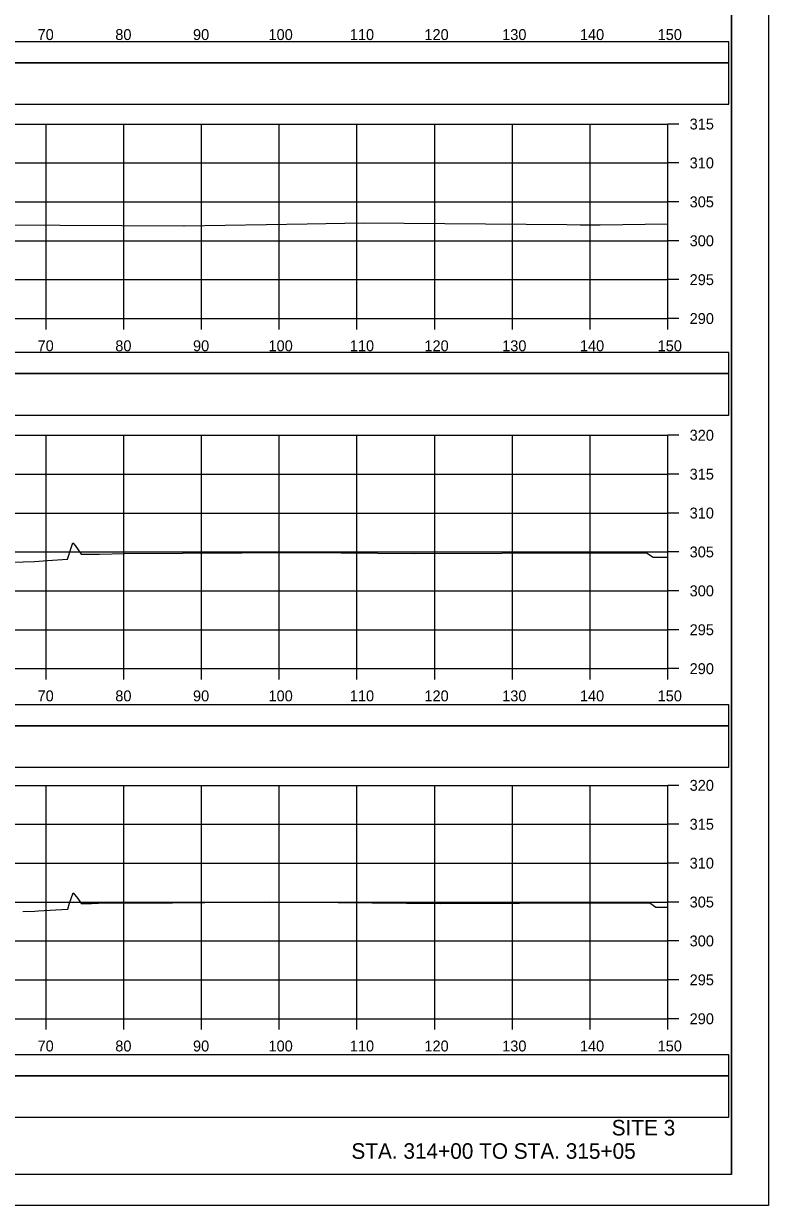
# Model space of a CAD drawing. Extents: x 1370538 to 1372872, y 376220 to 381127.
# Drawn here: x 1371442.4 to 1371538.2, y 378262.5 to 378414.4 of the extents above; entities that cross this region are included whole.
import ezdxf

# ---------------------------------------------------------------- set-up
doc = ezdxf.new("R2010")
doc.units = 0
for name, color, linetype in [('R_Border Notes', 7, 'Continuous'), ('R_Border PE', 7, 'Continuous'), ('R_Border Prem', 7, 'Continuous'), ('R_Dimension', 7, 'Continuous'), ('R_Grid', 7, 'Continuous'), ('R_Horz Alg Annot', 7, 'Continuous'), ('R_No Plot', 7, 'Continuous'), ('R_Proposed Road', 7, 'Continuous')]:
    doc.layers.add(name, color=color, linetype=linetype)

msp = doc.modelspace()

# ---------------------------------------------------------------- linework, layer by layer
at = {"layer": 'R_Border Notes'}
for q in [(1371533.47, 378471.99), (1371217.29, 378266.53)]:
    msp.add_line((1371533.47, 378266.53), q, dxfattribs=at)
at = {"layer": 'R_Border Prem'}
for p, q in [((1371525.29, 378376.53), (1371525.29, 378401.53)), ((1371526.69, 378401.53), (1371525.29, 378401.53)), ((1371526.69, 378396.53), (1371525.29, 378396.53)), ((1371526.69, 378391.53), (1371525.29, 378391.53)), ((1371526.69, 378386.53), (1371525.29, 378386.53)), ((1371526.69, 378381.53), (1371525.29, 378381.53)), ((1371225.29, 378376.53), (1371525.29, 378376.53)), ((1371445.29, 378375.13), (1371445.29, 378376.53)), ((1371455.29, 378375.13), (1371455.29, 378376.53)), ((1371465.29, 378375.13), (1371465.29, 378376.53)), ((1371475.29, 378375.13), (1371475.29, 378376.53)), ((1371485.29, 378375.13), (1371485.29, 378376.53)), ((1371495.29, 378375.13), (1371495.29, 378376.53)), ((1371505.29, 378375.13), (1371505.29, 378376.53)), ((1371515.29, 378375.13), (1371515.29, 378376.53)), ((1371525.29, 378375.13), (1371525.29, 378376.53)), ((1371526.69, 378376.53), (1371525.29, 378376.53)), ((1371525.29, 378331.53), (1371525.29, 378361.53)), ((1371526.69, 378361.53), (1371525.29, 378361.53)), ((1371526.69, 378356.53), (1371525.29, 378356.53)), ((1371526.69, 378351.53), (1371525.29, 378351.53)), ((1371526.69, 378346.53), (1371525.29, 378346.53)), ((1371526.69, 378341.53), (1371525.29, 378341.53)), ((1371526.69, 378336.53), (1371525.29, 378336.53)), ((1371225.29, 378331.53), (1371525.29, 378331.53)), ((1371445.29, 378330.13), (1371445.29, 378331.53)), ((1371455.29, 378330.13), (1371455.29, 378331.53)), ((1371465.29, 378330.13), (1371465.29, 378331.53)), ((1371475.29, 378330.13), (1371475.29, 378331.53)), ((1371485.29, 378330.13), (1371485.29, 378331.53)), ((1371495.29, 378330.13), (1371495.29, 378331.53)), ((1371505.29, 378330.13), (1371505.29, 378331.53)), ((1371515.29, 378330.13), (1371515.29, 378331.53)), ((1371525.29, 378330.13), (1371525.29, 378331.53)), ((1371526.69, 378331.53), (1371525.29, 378331.53)), ((1371525.29, 378286.53), (1371525.29, 378316.53)), ((1371526.69, 378316.53), (1371525.29, 378316.53)), ((1371526.69, 378311.53), (1371525.29, 378311.53)), ((1371526.69, 378306.53), (1371525.29, 378306.53)), ((1371526.69, 378301.53), (1371525.29, 378301.53)), ((1371526.69, 378296.53), (1371525.29, 378296.53)), ((1371526.69, 378291.53), (1371525.29, 378291.53)), ((1371225.29, 378286.53), (1371525.29, 378286.53)), ((1371445.29, 378285.13), (1371445.29, 378286.53)), ((1371455.29, 378285.13), (1371455.29, 378286.53)), ((1371465.29, 378285.13), (1371465.29, 378286.53)), ((1371475.29, 378285.13), (1371475.29, 378286.53)), ((1371485.29, 378285.13), (1371485.29, 378286.53)), ((1371495.29, 378285.13), (1371495.29, 378286.53)), ((1371505.29, 378285.13), (1371505.29, 378286.53)), ((1371515.29, 378285.13), (1371515.29, 378286.53)), ((1371525.29, 378285.13), (1371525.29, 378286.53)), ((1371526.69, 378286.53), (1371525.29, 378286.53))]:
    msp.add_line(p, q, dxfattribs=at)
at = {"layer": 'R_Dimension'}
for points in [[(1371415.21, 378388.72), (1371463.03, 378388.44), (1371463.05, 378388.44), (1371463.07, 378388.44), (1371463.07, 378388.44), (1371463.07, 378388.44), (1371478.9, 378388.71), (1371486.15, 378388.84), (1371512.31, 378388.6), (1371514, 378388.58), (1371515.22, 378388.56), (1371515.57, 378388.56), (1371516.59, 378388.57), (1371525.29, 378388.71)], [(1371437.9, 378345.15), (1371443.81, 378345.31), (1371445.46, 378345.44), (1371448.06, 378345.59), (1371448.52, 378347.05), (1371448.75, 378347.72), (1371449.06, 378347.35), (1371449.79, 378346.24), (1371452.16, 378346.24), (1371455.38, 378346.35), (1371462.84, 378346.38), (1371470.47, 378346.41), (1371478.54, 378346.47), (1371492.68, 378346.35), (1371503.94, 378346.39), (1371522.53, 378346.42), (1371523.39, 378345.84), (1371525.29, 378345.84)], [(1371442.32, 378300.31), (1371443.83, 378300.36), (1371444.26, 378300.39), (1371448.08, 378300.6), (1371448.33, 378301.38), (1371448.77, 378302.72), (1371449.4, 378301.98), (1371449.81, 378301.35), (1371451.16, 378301.35), (1371452.99, 378301.41), (1371457.23, 378301.43), (1371461.57, 378301.44), (1371474.08, 378301.54), (1371496.02, 378301.35), (1371506.18, 378301.39), (1371522.97, 378301.41), (1371523.75, 378300.89), (1371525.29, 378300.89)]]:
    msp.add_lwpolyline(points, dxfattribs=at)
at = {"layer": 'R_Grid'}
for p, q in [((1371225.29, 378401.53), (1371525.29, 378401.53)), ((1371445.29, 378376.53), (1371445.29, 378401.53)), ((1371455.29, 378376.53), (1371455.29, 378401.53)), ((1371465.29, 378376.53), (1371465.29, 378401.53)), ((1371475.29, 378376.53), (1371475.29, 378401.53)), ((1371485.29, 378376.53), (1371485.29, 378401.53)), ((1371495.29, 378376.53), (1371495.29, 378401.53)), ((1371505.29, 378376.53), (1371505.29, 378401.53)), ((1371515.29, 378376.53), (1371515.29, 378401.53)), ((1371525.29, 378376.53), (1371525.29, 378401.53)), ((1371225.29, 378396.53), (1371525.29, 378396.53)), ((1371225.29, 378391.53), (1371525.29, 378391.53)), ((1371225.29, 378386.53), (1371525.29, 378386.53)), ((1371225.29, 378381.53), (1371525.29, 378381.53)), ((1371225.29, 378376.53), (1371525.29, 378376.53)), ((1371225.29, 378361.53), (1371525.29, 378361.53)), ((1371445.29, 378331.53), (1371445.29, 378361.53)), ((1371455.29, 378331.53), (1371455.29, 378361.53)), ((1371465.29, 378331.53), (1371465.29, 378361.53)), ((1371475.29, 378331.53), (1371475.29, 378361.53)), ((1371485.29, 378331.53), (1371485.29, 378361.53)), ((1371495.29, 378331.53), (1371495.29, 378361.53)), ((1371505.29, 378331.53), (1371505.29, 378361.53)), ((1371515.29, 378331.53), (1371515.29, 378361.53)), ((1371525.29, 378331.53), (1371525.29, 378361.53)), ((1371225.29, 378356.53), (1371525.29, 378356.53)), ((1371225.29, 378351.53), (1371525.29, 378351.53)), ((1371225.29, 378346.53), (1371525.29, 378346.53)), ((1371225.29, 378341.53), (1371525.29, 378341.53)), ((1371225.29, 378336.53), (1371525.29, 378336.53)), ((1371225.29, 378331.53), (1371525.29, 378331.53)), ((1371225.29, 378316.53), (1371525.29, 378316.53)), ((1371445.29, 378286.53), (1371445.29, 378316.53)), ((1371455.29, 378286.53), (1371455.29, 378316.53)), ((1371465.29, 378286.53), (1371465.29, 378316.53)), ((1371475.29, 378286.53), (1371475.29, 378316.53)), ((1371485.29, 378286.53), (1371485.29, 378316.53)), ((1371495.29, 378286.53), (1371495.29, 378316.53)), ((1371505.29, 378286.53), (1371505.29, 378316.53)), ((1371515.29, 378286.53), (1371515.29, 378316.53)), ((1371525.29, 378286.53), (1371525.29, 378316.53)), ((1371225.29, 378311.53), (1371525.29, 378311.53)), ((1371225.29, 378306.53), (1371525.29, 378306.53)), ((1371225.29, 378301.53), (1371525.29, 378301.53)), ((1371225.29, 378296.53), (1371525.29, 378296.53)), ((1371225.29, 378291.53), (1371525.29, 378291.53)), ((1371225.29, 378286.53), (1371525.29, 378286.53))]:
    msp.add_line(p, q, dxfattribs=at)
at = {"layer": 'R_Horz Alg Annot'}
for points in [[(1371218, 378409.4), (1371533.13, 378409.4), (1371533.13, 378412.11), (1371218, 378412.11)], [(1371218, 378404.08), (1371533.13, 378404.08), (1371533.13, 378409.4), (1371218, 378409.4)], [(1371218, 378369.45), (1371533.13, 378369.45), (1371533.13, 378372.15), (1371218, 378372.15)], [(1371218, 378364.13), (1371533.13, 378364.13), (1371533.13, 378369.45), (1371218, 378369.45)], [(1371218, 378324.2), (1371533.13, 378324.2), (1371533.13, 378326.9), (1371218, 378326.9)], [(1371218, 378318.87), (1371533.13, 378318.87), (1371533.13, 378324.2), (1371218, 378324.2)], [(1371218, 378279.19), (1371533.13, 378279.19), (1371533.13, 378281.89), (1371218, 378281.89)], [(1371218, 378273.87), (1371533.13, 378273.87), (1371533.13, 378279.19), (1371218, 378279.19)]]:
    msp.add_lwpolyline(points, close=True, dxfattribs=at)
at = {"layer": 'R_No Plot'}
msp.add_line((1371204.89, 378262.55), (1371538.22, 378262.55), dxfattribs=at)
for points in [[(1371204.88, 378475.88), (1371538.22, 378475.88), (1371538.22, 378262.54), (1371204.88, 378262.54)], [(1371451.21, 378471.99), (1371451.21, 378462.11), (1371486.94, 378462.11), (1371486.94, 378459.19), (1371510.14, 378459.19), (1371510.14, 378434.85), (1371533.47, 378434.85), (1371533.47, 378266.53), (1371217.29, 378266.53), (1371217.29, 378471.99)]]:
    msp.add_lwpolyline(points, close=True, dxfattribs=at)

# ---------------------------------------------------------------- texts
at = {"layer": 'R_Border PE'}
for s, p in [('70', (1371444.2, 378412.33)), ('80', (1371454.2, 378412.33)), ('90', (1371464.2, 378412.33)), ('100', (1371473.91, 378412.33)), ('110', (1371484.37, 378412.33)), ('120', (1371493.97, 378412.33)), ('130', (1371503.97, 378412.33)), ('140', (1371513.97, 378412.33)), ('150', (1371523.97, 378412.33)), ('315', (1371528.09, 378400.83)), ('310', (1371528.09, 378395.83)), ('305', (1371528.09, 378390.83)), ('300', (1371528.09, 378385.83)), ('295', (1371528.09, 378380.83)), ('290', (1371528.09, 378375.83)), ('70', (1371444.2, 378372.33)), ('80', (1371454.2, 378372.33)), ('90', (1371464.2, 378372.33)), ('100', (1371473.91, 378372.33)), ('110', (1371484.37, 378372.33)), ('120', (1371493.97, 378372.33)), ('130', (1371503.97, 378372.33)), ('140', (1371513.97, 378372.33)), ('150', (1371523.97, 378372.33)), ('320', (1371528.09, 378360.83)), ('315', (1371528.09, 378355.83)), ('310', (1371528.09, 378350.83)), ('305', (1371528.09, 378345.83)), ('300', (1371528.09, 378340.83)), ('295', (1371528.09, 378335.83)), ('290', (1371528.09, 378330.83)), ('70', (1371444.2, 378327.33)), ('80', (1371454.2, 378327.33)), ('90', (1371464.2, 378327.33)), ('100', (1371473.91, 378327.33)), ('110', (1371484.37, 378327.33)), ('120', (1371493.97, 378327.33)), ('130', (1371503.97, 378327.33)), ('140', (1371513.97, 378327.33)), ('150', (1371523.97, 378327.33)), ('320', (1371528.09, 378315.83)), ('315', (1371528.09, 378310.83)), ('310', (1371528.09, 378305.83)), ('305', (1371528.09, 378300.83)), ('300', (1371528.09, 378295.83)), ('295', (1371528.09, 378290.83)), ('290', (1371528.09, 378285.83)), ('70', (1371444.2, 378282.33)), ('80', (1371454.2, 378282.33)), ('90', (1371464.2, 378282.33)), ('100', (1371473.91, 378282.33)), ('110', (1371484.37, 378282.33)), ('120', (1371493.97, 378282.33)), ('130', (1371503.97, 378282.33)), ('140', (1371513.97, 378282.33)), ('150', (1371523.97, 378282.33))]:
    msp.add_text(s, height=1.4, dxfattribs=at).set_placement(p)
at = {"layer": 'R_Proposed Road'}
for s, p in [('SITE 3', (1371518.06, 378271.53)), ('STA. 314+00 TO STA. 315+05', (1371484.58, 378268.53))]:
    msp.add_text(s, height=2, dxfattribs=at).set_placement(p)

doc.saveas('drawing.dxf')
